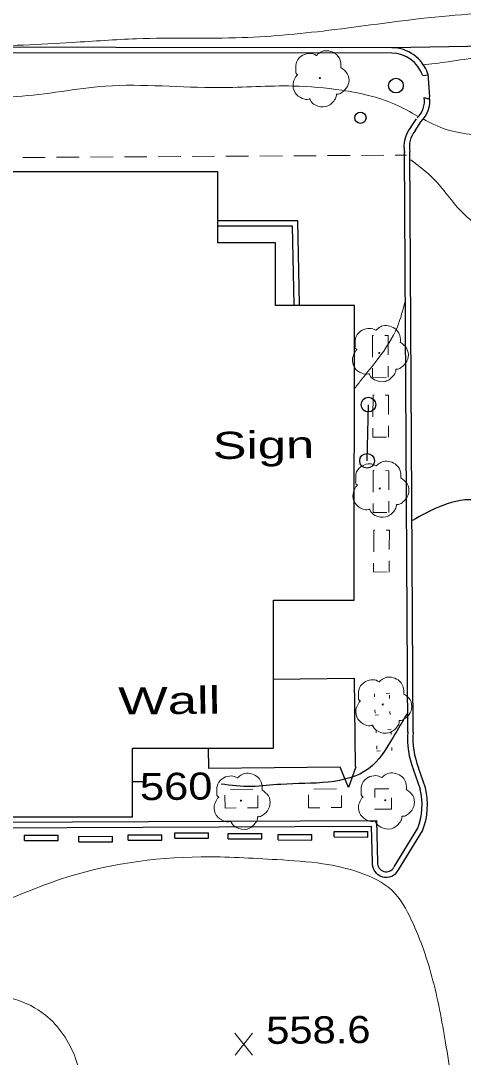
# Model space of a CAD drawing. Extents: x 2361708 to 2370558, y 6977955 to 6991887.
# Drawn here: x 2365302.6 to 2365381, y 6981931.3 to 6982114.9 of the extents above; entities that cross this region are included whole.
import ezdxf
from ezdxf.enums import TextEntityAlignment as Align

# ---------------------------------------------------------------- set-up
doc = ezdxf.new("R2010")
doc.units = 0
doc.header["$LTSCALE"] = 1.9
doc.linetypes.add('DOTTED', pattern=[1.5, 0.3, -1.2])
for name, color, linetype, lineweight in [('11', 7, 'Continuous', 25), ('13', 7, 'Continuous', 13), ('18', 7, 'Continuous', 25), ('2', 7, 'Continuous', 25), ('20', 7, 'Continuous', 25), ('21', 7, 'Continuous', 25), ('23', 7, 'Continuous', 25), ('29', 7, 'Continuous', 13), ('31', 7, 'Continuous', 13), ('35', 7, 'Continuous', 13)]:
    doc.layers.add(name, color=color, linetype=linetype, lineweight=lineweight)

msp = doc.modelspace()

# ---------------------------------------------------------------- linework, layer by layer
at = {"layer": '11'}
msp.add_lwpolyline([(2365245.104, 6981973.887), (2365322.397, 6981973.873), (2365322.401, 6981986.073), (2365347.372, 6981986.061), (2365347.383, 6982012.263), (2365361.684, 6982012.259), (2365361.697, 6982064.481), (2365347.716, 6982064.488), (2365347.721, 6982075.569), (2365337.48, 6982075.572), (2365337.48, 6982088.142), (2365281.227, 6982088.157), (2365281.224, 6982074.836), (2365258.733, 6982074.842), (2365258.715, 6982043.15), (2365245.154, 6982043.161)], close=True, dxfattribs=at)
at = {"layer": '13'}
for p, q in [((2365306.944, 6982090.712), (2365302.944, 6982090.684)), ((2365312.944, 6982090.749), (2365308.944, 6982090.721)), ((2365318.944, 6982090.786), (2365314.944, 6982090.758)), ((2365324.944, 6982090.823), (2365320.944, 6982090.795)), ((2365330.944, 6982090.86), (2365326.944, 6982090.832)), ((2365336.944, 6982090.897), (2365332.944, 6982090.869)), ((2365342.944, 6982090.935), (2365338.944, 6982090.906)), ((2365348.944, 6982090.972), (2365344.944, 6982090.943)), ((2365354.944, 6982091.009), (2365350.944, 6982090.98)), ((2365360.944, 6982091.046), (2365356.944, 6982091.018)), ((2365366.944, 6982091.083), (2365362.944, 6982091.055)), ((2365370.944, 6982091.101), (2365368.944, 6982091.092)), ((2365367.668, 6982051.748), (2365367.679, 6982053.748)), ((2365367.739, 6982041.148), (2365367.75, 6982043.148)), ((2365367.776, 6982027.797), (2365367.787, 6982029.798)), ((2365367.866, 6982017.258), (2365367.877, 6982019.258)), ((2365343.731, 6981978.786), (2365339.732, 6981978.748)), ((2365358.532, 6981978.827), (2365354.532, 6981978.789)), ((2365338.761, 6981977.719), (2365338.783, 6981975.439)), ((2365353.562, 6981977.76), (2365353.583, 6981975.48)), ((2365368.246, 6981975.27), (2365368.247, 6981977.27)), ((2365338.783, 6981975.439), (2365340.783, 6981975.458)), ((2365353.583, 6981975.48), (2365355.583, 6981975.499))]:
    msp.add_line(p, q, dxfattribs=at)
for points in [[(2365365.107, 6982059.173), (2365364.937, 6982059.172), (2365364.924, 6982055.342)], [(2365367.69, 6982055.748), (2365367.698, 6982059.158), (2365367.108, 6982059.163)], [(2365364.913, 6982053.342), (2365364.908, 6982051.761), (2365367.328, 6982051.745)], [(2365365.178, 6982048.574), (2365365.008, 6982048.572), (2365364.994, 6982044.742)], [(2365367.761, 6982045.149), (2365367.768, 6982048.559), (2365367.178, 6982048.563)], [(2365364.984, 6982042.742), (2365364.979, 6982041.162), (2365367.399, 6982041.145)], [(2365365.215, 6982035.224), (2365365.045, 6982035.222), (2365365.032, 6982031.392)], [(2365367.798, 6982031.798), (2365367.805, 6982035.208), (2365367.216, 6982035.213)], [(2365365.021, 6982029.391), (2365365.016, 6982027.811), (2365367.436, 6982027.794)], [(2365365.305, 6982024.684), (2365365.135, 6982024.682), (2365365.122, 6982020.852)], [(2365367.888, 6982021.258), (2365367.896, 6982024.669), (2365367.306, 6982024.673)], [(2365365.111, 6982018.852), (2365365.106, 6982017.272), (2365367.527, 6982017.255)], [(2365367.812, 6981978.825), (2365365.342, 6981978.832), (2365365.337, 6981977.302)], [(2365342.783, 6981975.477), (2365344.623, 6981975.494), (2365344.602, 6981977.655)], [(2365357.583, 6981975.518), (2365359.423, 6981975.536), (2365359.403, 6981977.695)], [(2365365.336, 6981975.302), (2365365.336, 6981975.272), (2365368.246, 6981975.27)]]:
    msp.add_lwpolyline(points, dxfattribs=at)
at = {"layer": '13', "linetype": 'DOTTED'}
for points in [[(2365365.252, 6981995.692), (2365365.377, 6981991.913), (2365368.027, 6981991.998), (2365367.901, 6981995.777)], [(2365365.552, 6981989.315), (2365365.678, 6981985.536), (2365368.328, 6981985.62), (2365368.201, 6981989.4)]]:
    msp.add_lwpolyline(points, close=True, dxfattribs=at)
at = {"layer": '18'}
for points in [[(2365347.336, 6981998.281), (2365361.685, 6981998.448), (2365361.864, 6981982.799)], [(2365359.165, 6981982.693), (2365335.896, 6981982.432), (2365335.851, 6981986.081)], [(2365361.935, 6981982.73), (2365360.659, 6981979.087), (2365359.165, 6981982.693)]]:
    msp.add_lwpolyline(points, dxfattribs=at)
at = {"layer": '2'}
for p, q in [((2365411.128, 6982110.804), (2365368.322, 6982110.137)), ((2365373.8, 6982105.209), (2365374.759, 6982105.308)), ((2365374.707, 6982105.517), (2365375.036, 6982101.42)), ((2365374.087, 6982101.291), (2365375, 6982101)), ((2365371.657, 6982095.958), (2365372.682, 6982097.538)), ((2365372.463, 6982095.435), (2365373.488, 6982097.016)), ((2365371.147, 6981988.888), (2365370.568, 6982091.717)), ((2365372.107, 6981988.897), (2365371.528, 6982091.726)), ((2365373.384, 6981978.728), (2365372.159, 6981982.257)), ((2365374.291, 6981979.047), (2365373.067, 6981982.576)), ((2365329.903, 6981970.124), (2365329.904, 6981971.084)), ((2365329.904, 6981971.084), (2365335.865, 6981971.071)), ((2365335.864, 6981970.111), (2365335.865, 6981971.071)), ((2365339.345, 6981969.994), (2365339.346, 6981970.954)), ((2365339.346, 6981970.954), (2365345.306, 6981970.941)), ((2365345.305, 6981969.981), (2365345.306, 6981970.941)), ((2365348.197, 6981969.798), (2365348.198, 6981970.758)), ((2365348.198, 6981970.758), (2365354.158, 6981970.745)), ((2365354.158, 6981969.785), (2365354.158, 6981970.745)), ((2365358.133, 6981970.323), (2365358.134, 6981971.283)), ((2365358.134, 6981971.283), (2365364.094, 6981971.27)), ((2365364.093, 6981970.31), (2365364.094, 6981971.27)), ((2365368.724, 6981965.023), (2365372.938, 6981971.894)), ((2365369.538, 6981964.521), (2365373.754, 6981971.392)), ((2365303.236, 6981969.7), (2365303.237, 6981970.66)), ((2365303.236, 6981969.7), (2365309.196, 6981969.687)), ((2365303.237, 6981970.66), (2365309.197, 6981970.647)), ((2365309.196, 6981969.687), (2365309.197, 6981970.647)), ((2365312.879, 6981970.442), (2365318.84, 6981970.429)), ((2365312.879, 6981969.482), (2365312.879, 6981970.442)), ((2365312.879, 6981969.482), (2365318.839, 6981969.469)), ((2365318.839, 6981969.469), (2365318.84, 6981970.429)), ((2365321.646, 6981969.746), (2365321.647, 6981970.706)), ((2365321.646, 6981969.746), (2365327.607, 6981969.732)), ((2365321.647, 6981970.706), (2365327.608, 6981970.692)), ((2365327.607, 6981969.732), (2365327.608, 6981970.692)), ((2365329.903, 6981970.124), (2365335.864, 6981970.111)), ((2365339.345, 6981969.994), (2365345.305, 6981969.981)), ((2365348.197, 6981969.798), (2365354.158, 6981969.785)), ((2365358.133, 6981970.323), (2365364.093, 6981970.31))]:
    msp.add_line(p, q, dxfattribs=at)
for points in [[(2365368.322, 6982110.137), (2365270.457, 6982110.215), (2365203.488, 6982109.787)], [(2365368.322, 6982109.177), (2365270.456, 6982109.255), (2365203.497, 6982108.828)], [(2365193.312, 6982099.82), (2365239.211, 6982100.157), (2365239.197, 6982091.107), (2365244.139, 6982090.994), (2365244.395, 6981972.691), (2365365.635, 6981973.215), (2365365.805, 6981965.846)], [(2365193.322, 6982098.86), (2365238.25, 6982099.188), (2365238.236, 6982090.168), (2365243.178, 6982090.055), (2365243.434, 6981971.731), (2365364.695, 6981972.245), (2365364.846, 6981965.827)], [(2365351.975, 6982064.659), (2365351.683, 6982079.467), (2365337.363, 6982079.471)], [(2365351.014, 6982064.64), (2365350.742, 6982078.508), (2365337.612, 6982078.503)]]:
    msp.add_lwpolyline(points, dxfattribs=at)
for centre, radius, start, end in [((2365368.285, 6982103.364), 5.813, 18.53883, 89.6822), ((2365368.285, 6982103.364), 6.773, 18.53883, 89.6822), ((2365369.99, 6982100.718), 4.133, 313.36768, 7.92934), ((2365369.99, 6982100.718), 5.093, 313.36768, 7.92934), ((2365375.813, 6982092.618), 5.337, 139.93792, 191.75552), ((2365375.813, 6982092.618), 4.377, 139.93792, 191.75552), ((2365386.255, 6981987.812), 15.15, 175.61667, 201.65573), ((2365386.255, 6981987.812), 14.19, 175.61667, 201.65573), ((2365362.069, 6981976.058), 11.621, 338.23027, 13.74501), ((2365362.069, 6981976.058), 12.581, 338.23027, 13.74501), ((2365367.332, 6981965.682), 2.491, 176.66337, 332.25563), ((2365367.332, 6981965.682), 1.531, 176.66337, 332.25563), ((2311712.864, 7003141.482), 57778.093, 338.23902, 338.46862)]:
    msp.add_arc(centre, radius, start, end, dxfattribs=at)
at = {"layer": '20'}
msp.add_circle((2365362.76, 6982097.733), 1, dxfattribs=at)
at = {"layer": '21'}
msp.add_line((2365363.959, 6982036.942), (2365364.204, 6982046.895), dxfattribs=at)
for centre in [(2365364.194, 6982046.905), (2365363.949, 6982036.952)]:
    msp.add_circle(centre, 1.3, dxfattribs=at)
at = {"layer": '23'}
msp.add_circle((2365369.066, 6982103.424), 1.3, dxfattribs=at)
at = {"layer": '29'}
for centre in [(2365355.583, 6982104.755), (2365366.107, 6982056.063), (2365366.196, 6982032.053), (2365366.71, 6981993.796), (2365341.611, 6981976.766), (2365367.181, 6981976.829)]:
    msp.add_circle(centre, 0.1, dxfattribs=at)
for points in [[(2365351.617, 6982105.328), (2365351.637, 6982105.338), (2365351.556, 6982105.407), (2365351.32, 6982106.035), (2365351.358, 6982107.315), (2365352.246, 6982108.614), (2365353.552, 6982109.096), (2365354.674, 6982108.907), (2365354.905, 6982108.779), (2365354.974, 6982108.78), (2365355.024, 6982108.82), (2365355.372, 6982109.114), (2365356.237, 6982109.562), (2365357.448, 6982109.493), (2365358.563, 6982108.904), (2365359.298, 6982107.481), (2365359.306, 6982106.62)], [(2365359.295, 6982106.641), (2365360.435, 6982105.581), (2365360.72, 6982103.994), (2365360.013, 6982102.667), (2365359.358, 6982102.121), (2365358.69, 6982101.905), (2365358.54, 6982101.893), (2365358.521, 6982101.783), (2365358.2, 6982100.88), (2365356.661, 6982099.715), (2365354.768, 6982099.997), (2365353.869, 6982100.939), (2365353.798, 6982101.068), (2365353.678, 6982101.047), (2365352.467, 6982101.165), (2365351.198, 6982102.163), (2365350.852, 6982103.8), (2365351.222, 6982104.824), (2365351.548, 6982105.267), (2365351.617, 6982105.317)], [(2365362.141, 6982056.635), (2365362.161, 6982056.646), (2365362.081, 6982056.715), (2365361.844, 6982057.342), (2365361.882, 6982058.623), (2365362.77, 6982059.922), (2365364.075, 6982060.404), (2365365.198, 6982060.215), (2365365.428, 6982060.087), (2365365.498, 6982060.088), (2365365.548, 6982060.128), (2365365.895, 6982060.421), (2365366.761, 6982060.87), (2365367.972, 6982060.801), (2365369.088, 6982060.212), (2365369.821, 6982058.789), (2365369.829, 6982057.928)], [(2365369.819, 6982057.948), (2365370.959, 6982056.889), (2365371.244, 6982055.302), (2365370.537, 6982053.975), (2365369.882, 6982053.429), (2365369.214, 6982053.213), (2365369.065, 6982053.201), (2365369.046, 6982053.091), (2365368.724, 6982052.188), (2365367.185, 6982051.023), (2365365.292, 6982051.305), (2365364.393, 6982052.247), (2365364.322, 6982052.376), (2365364.202, 6982052.355), (2365362.991, 6982052.473), (2365361.721, 6982053.471), (2365361.376, 6982055.108), (2365361.746, 6982056.131), (2365362.072, 6982056.575), (2365362.141, 6982056.626)], [(2365362.23, 6982032.625), (2365362.25, 6982032.635), (2365362.169, 6982032.704), (2365361.933, 6982033.332), (2365361.971, 6982034.613), (2365362.859, 6982035.911), (2365364.164, 6982036.394), (2365365.286, 6982036.204), (2365365.517, 6982036.076), (2365365.587, 6982036.077), (2365365.637, 6982036.117), (2365365.984, 6982036.411), (2365366.85, 6982036.859), (2365368.061, 6982036.791), (2365369.176, 6982036.201), (2365369.91, 6982034.778), (2365369.918, 6982033.918)], [(2365369.908, 6982033.938), (2365371.048, 6982032.879), (2365371.333, 6982031.292), (2365370.626, 6982029.964), (2365369.971, 6982029.418), (2365369.303, 6982029.202), (2365369.153, 6982029.191), (2365369.134, 6982029.081), (2365368.813, 6982028.177), (2365367.274, 6982027.013), (2365365.381, 6982027.295), (2365364.482, 6982028.236), (2365364.41, 6982028.366), (2365364.291, 6982028.344), (2365363.079, 6982028.463), (2365361.81, 6982029.461), (2365361.465, 6982031.098), (2365361.835, 6982032.122), (2365362.16, 6982032.565), (2365362.23, 6982032.615)], [(2365362.744, 6981994.368), (2365362.764, 6981994.378), (2365362.683, 6981994.448), (2365362.447, 6981995.075), (2365362.485, 6981996.356), (2365363.373, 6981997.654), (2365364.678, 6981998.136), (2365365.8, 6981997.947), (2365366.031, 6981997.82), (2365366.101, 6981997.82), (2365366.151, 6981997.861), (2365366.498, 6981998.154), (2365367.364, 6981998.602), (2365368.575, 6981998.533), (2365369.69, 6981997.945), (2365370.424, 6981996.521), (2365370.432, 6981995.661)], [(2365370.422, 6981995.681), (2365371.562, 6981994.622), (2365371.847, 6981993.035), (2365371.14, 6981991.708), (2365370.485, 6981991.162), (2365369.817, 6981990.945), (2365369.667, 6981990.934), (2365369.648, 6981990.824), (2365369.327, 6981989.921), (2365367.788, 6981988.756), (2365365.895, 6981989.038), (2365364.996, 6981989.979), (2365364.925, 6981990.109), (2365364.805, 6981990.088), (2365363.594, 6981990.206), (2365362.324, 6981991.204), (2365361.979, 6981992.841), (2365362.349, 6981993.864), (2365362.675, 6981994.308), (2365362.744, 6981994.358)], [(2365363.216, 6981977.402), (2365363.236, 6981977.412), (2365363.155, 6981977.481), (2365362.919, 6981978.109), (2365362.957, 6981979.389), (2365363.844, 6981980.688), (2365365.15, 6981981.171), (2365366.272, 6981980.981), (2365366.503, 6981980.853), (2365366.573, 6981980.854), (2365366.623, 6981980.894), (2365366.97, 6981981.188), (2365367.836, 6981981.636), (2365369.046, 6981981.568), (2365370.162, 6981980.978), (2365370.895, 6981979.555), (2365370.904, 6981978.695)], [(2365337.645, 6981977.338), (2365337.665, 6981977.348), (2365337.584, 6981977.418), (2365337.348, 6981978.046), (2365337.386, 6981979.326), (2365338.274, 6981980.625), (2365339.579, 6981981.107), (2365340.701, 6981980.918), (2365340.932, 6981980.79), (2365341.002, 6981980.791), (2365341.052, 6981980.831), (2365341.399, 6981981.124), (2365342.265, 6981981.573), (2365343.475, 6981981.504), (2365344.591, 6981980.915), (2365345.325, 6981979.491), (2365345.333, 6981978.631)], [(2365345.323, 6981978.651), (2365346.463, 6981977.592), (2365346.748, 6981976.005), (2365346.041, 6981974.678), (2365345.386, 6981974.132), (2365344.718, 6981973.916), (2365344.568, 6981973.904), (2365344.549, 6981973.794), (2365344.227, 6981972.891), (2365342.689, 6981971.726), (2365340.796, 6981972.008), (2365339.897, 6981972.95), (2365339.826, 6981973.079), (2365339.706, 6981973.058), (2365338.495, 6981973.176), (2365337.225, 6981974.175), (2365336.879, 6981975.811), (2365337.25, 6981976.835), (2365337.576, 6981977.278), (2365337.645, 6981977.328)], [(2365370.893, 6981978.715), (2365372.033, 6981977.656), (2365372.319, 6981976.068), (2365371.611, 6981974.741), (2365370.956, 6981974.195), (2365370.288, 6981973.979), (2365370.138, 6981973.968), (2365370.12, 6981973.857), (2365369.798, 6981972.954), (2365368.259, 6981971.789), (2365366.366, 6981972.072), (2365365.467, 6981973.013), (2365365.396, 6981973.142), (2365365.276, 6981973.121), (2365364.065, 6981973.24), (2365362.796, 6981974.238), (2365362.45, 6981975.874), (2365362.82, 6981976.898), (2365363.146, 6981977.341), (2365363.216, 6981977.392)]]:
    msp.add_spline(points, degree=3, dxfattribs=at)
at = {"layer": '31', "lineweight": 25}
msp.add_line((2365324.338, 6981980.112), (2365322.288, 6981980.113), dxfattribs=at)
at = {"layer": '31'}
for p, q in [((2365343.659, 6981931.693), (2365340.543, 6981935.544)), ((2365340.58, 6981931.664), (2365343.623, 6981935.573))]:
    msp.add_line(p, q, dxfattribs=at)
at = {"layer": '31', "lineweight": 25}
for points in [[(2365410.227, 6981973.309), (2365410.038, 6981978.497), (2365410.159, 6981997.22), (2365405.175, 6982009.123), (2365399.768, 6982019.372), (2365391.472, 6982026.193), (2365382.815, 6982030.051), (2365376.617, 6982028.762), (2365371.97, 6982026.378)], [(2365371.085, 6981992.257), (2365368.565, 6981988.003), (2365364.218, 6981982.412), (2365357.14, 6981980.044), (2365348.694, 6981979.643), (2365343.487, 6981979.254), (2365338.073, 6981979.672)]]:
    msp.add_spline(points, degree=3, dxfattribs=at)
at = {"layer": '35'}
for points in [[(2365109.402, 6981545.775), (2365131.445, 6981549.695), (2365161.361, 6981558.69), (2365183.98, 6981565.236), (2365205.03, 6981568.516), (2365226.001, 6981575.846), (2365237.057, 6981582.612), (2365238.603, 6981584.107), (2365246.477, 6981596.342), (2365250.991, 6981609.596), (2365252.103, 6981624.127), (2365255.069, 6981626.605), (2365256.719, 6981621.351), (2365258.448, 6981613.117), (2365261.221, 6981603.383), (2365265.255, 6981596.641), (2365271.824, 6981589.383), (2365278.776, 6981581.829), (2365281.528, 6981581.695), (2365286.668, 6981587.994), (2365291.277, 6981595.538), (2365295.634, 6981606.37), (2365294.418, 6981619.56), (2365297.594, 6981630.56), (2365302.729, 6981642.64), (2365306.356, 6981653.435), (2365314.989, 6981660.607), (2365319.684, 6981668.452), (2365316.213, 6981678.01), (2365313.166, 6981687.181), (2365319.859, 6981697.416), (2365326.64, 6981699.43), (2365334.746, 6981700.878), (2365340.746, 6981706.185), (2365344.848, 6981713.384), (2365343.021, 6981718.297), (2365336.43, 6981721.484), (2365326.656, 6981722.951), (2365318.433, 6981723.173), (2365315.821, 6981723.418), (2365315.802, 6981726.479), (2365324.911, 6981732.925), (2365332.876, 6981735.501), (2365340.075, 6981734.64), (2365345.289, 6981734.229), (2365351.365, 6981734.717), (2365358.386, 6981733.654), (2365363.512, 6981730.903), (2365369.601, 6981729.971), (2365376.122, 6981731.963), (2365379.61, 6981730.146), (2365382.411, 6981727.882), (2365389.236, 6981725.317), (2365398.373, 6981725.724), (2365405.868, 6981729.456), (2365411.448, 6981735.799), (2365417.037, 6981742.263), (2365423.139, 6981751.501), (2365430.096, 6981763.358), (2365437.549, 6981776.74), (2365442.735, 6981787.749), (2365451.802, 6981805.876), (2365462.536, 6981827.68), (2365472.723, 6981851.068), (2365482.619, 6981872.653), (2365490.274, 6981889.937), (2365499.076, 6981911.882), (2365507.143, 6981931.109), (2365515.756, 6981950.863), (2365524.787, 6981972.82), (2365534.052, 6981995.429), (2365542.203, 6982016.418), (2365552.168, 6982042.193), (2365561.205, 6982063.57), (2365569.506, 6982083.49), (2365577.612, 6982102.849), (2365582.115, 6982114.062), (2365586.885, 6982124.658), (2365593.024, 6982140.547), (2365599.035, 6982155.155), (2365606.868, 6982174.82), (2365616.146, 6982197.14), (2365625.505, 6982219.35), (2365634.428, 6982240.106), (2365646.14, 6982267.319), (2365654.345, 6982287.778), (2365666.243, 6982315.483), (2365672.813, 6982330.146), (2365677.178, 6982340.138), (2365680.28, 6982347.317)], [(2365676.186, 6982348.709), (2365669.524, 6982334.195), (2365660.54, 6982313.568), (2365647.814, 6982282.625), (2365636.978, 6982257.941), (2365624.242, 6982229.118), (2365608.097, 6982192.873), (2365596.749, 6982165.264), (2365587.378, 6982141.123), (2365580.804, 6982124.64), (2365574.754, 6982112.072), (2365565.831, 6982089.246), (2365556.537, 6982067.486), (2365547.388, 6982045.268), (2365538.366, 6982023.351), (2365526.705, 6981994.089), (2365516.823, 6981968.973), (2365506.885, 6981943.507), (2365496.498, 6981920.078), (2365483.67, 6981891.414), (2365473.587, 6981868.507), (2365463.718, 6981846.302), (2365454.424, 6981827.803), (2365449.108, 6981817.892), (2365443.404, 6981807.797), (2365436.869, 6981803.004), (2365431.569, 6981800.864), (2365422.232, 6981800.525), (2365410.028, 6981800.899), (2365403.44, 6981804.846), (2365394.142, 6981809.808), (2365385.386, 6981812.485), (2365377.881, 6981816.163), (2365373.829, 6981821.645), (2365372.596, 6981830.304), (2365373.713, 6981842.185), (2365376.925, 6981856.696), (2365378.206, 6981872.369), (2365380.617, 6981890.113), (2365381.49, 6981905.622), (2365379.952, 6981920.048), (2365377.978, 6981933.11), (2365375.626, 6981944.839), (2365371.844, 6981955.533), (2365368.393, 6981960.83), (2365362.593, 6981964.035), (2365356.108, 6981965.574), (2365347.981, 6981966.306), (2365334.535, 6981966.799), (2365309.632, 6981962.831), (2365298.232, 6981958.532), (2365286.767, 6981951.633), (2365286.326, 6981944.389), (2365287.51, 6981942.909), (2365295.017, 6981942.241), (2365306.95, 6981938.784), (2365312.304, 6981931.095), (2365312.889, 6981918.96), (2365308.949, 6981908.552), (2365306.75, 6981895.771)], [(2365677.892, 6982348.085), (2365672.529, 6982335.833), (2365660.648, 6982307.429), (2365646.837, 6982274.926), (2365635.036, 6982246.682), (2365622.081, 6982216.677), (2365611.669, 6982191.577), (2365599.553, 6982163.83), (2365592.687, 6982146.534), (2365586.249, 6982129.432), (2365581.466, 6982118.156), (2365576.288, 6982105.356), (2365564.068, 6982076.909), (2365552.851, 6982051.33), (2365543.267, 6982027.538), (2365531.634, 6981996.346), (2365522.275, 6981974.126), (2365508.88, 6981943.016), (2365498.407, 6981916.996), (2365486.732, 6981889.043), (2365472.681, 6981858.638), (2365460.458, 6981831.65), (2365451.237, 6981812.771), (2365440.214, 6981790.985), (2365431.973, 6981776.316), (2365426.085, 6981768.75), (2365419.614, 6981764.528), (2365407.216, 6981764.27), (2365393.489, 6981764.93), (2365388.697, 6981766.264), (2365384.846, 6981770.478), (2365379.432, 6981770.846), (2365371.905, 6981769.514), (2365366.159, 6981770.12), (2365363.621, 6981770.856)], [(2365326.783, 6981453.29), (2365329.976, 6981458.16), (2365344.053, 6981475.395), (2365361.918, 6981501.216), (2365372.671, 6981517.71), (2365385.111, 6981538.889), (2365397.296, 6981563.596), (2365407.375, 6981584.723), (2365416.119, 6981604.297), (2365426.44, 6981628.477), (2365436.776, 6981653.056), (2365445.98, 6981674.775), (2365453.326, 6981692.116), (2365458.767, 6981703.518), (2365463.027, 6981714.119), (2365466.907, 6981726.727), (2365470.863, 6981739.705), (2365476.646, 6981754.17), (2365484.6, 6981775.797), (2365493.674, 6981796.465), (2365502.219, 6981819.117), (2365510.893, 6981840.74), (2365521.377, 6981866.692), (2365530.302, 6981887.188), (2365538.13, 6981907.474), (2365547.935, 6981935.368), (2365557, 6981959.015), (2365565.863, 6981980.771), (2365572.485, 6981997.415), (2365579.94, 6982015.846), (2365585.681, 6982031.492), (2365590.885, 6982044.752), (2365597.257, 6982060.423), (2365604.626, 6982078.445), (2365613.142, 6982097.756), (2365620.363, 6982115.526), (2365626.825, 6982131.138), (2365634.8, 6982150.575), (2365643.428, 6982171.918), (2365650.153, 6982189.263), (2365659.494, 6982211.273), (2365667.482, 6982230.38), (2365675.981, 6982251.552), (2365685.231, 6982273.761), (2365693.814, 6982292.324), (2365702.299, 6982311.865), (2365708.915, 6982325.909), (2365713.381, 6982333.712)], [(2365285.582, 6982140.181), (2365299.201, 6982139.3), (2365322.919, 6982138.646), (2365343.29, 6982137.51), (2365363.096, 6982134.948), (2365388.801, 6982133.513), (2365416.137, 6982131.973), (2365429.989, 6982128.704), (2365432.417, 6982125.788), (2365429.949, 6982122.324), (2365414.928, 6982118.201), (2365396.16, 6982116.852), (2365378.469, 6982115.804), (2365358.211, 6982113.341), (2365341.794, 6982111.934), (2365323.115, 6982111.726), (2365311.721, 6982111.058), (2365294.397, 6982110.283)], [(2365373.712, 6982107.128), (2365378.297, 6982107.642), (2365383.999, 6982108.456), (2365391.349, 6982108.496), (2365395.164, 6982107.992), (2365398.66, 6982107.415), (2365402.452, 6982106.162)], [(2365372.988, 6982097.971), (2365368.828, 6982100.131), (2365359.474, 6982102.602), (2365350.826, 6982103.35), (2365337.699, 6982103.065), (2365317.595, 6982103.324), (2365301.851, 6982101.494), (2365285.169, 6982101.625), (2365275.585, 6982100.954), (2365255.913, 6982101.046), (2365245.182, 6982101.124), (2365235.817, 6982100.575), (2365231.091, 6982100.09)], [(2365400.251, 6982099.95), (2365397.61, 6982097.915), (2365385.03, 6982094.665), (2365375.802, 6982096.508), (2365373.843, 6982097.529)], [(2365442.367, 6981953.554), (2365442.927, 6981957.66), (2365442.549, 6981969.046), (2365443, 6981982.571), (2365448.121, 6982001.461), (2365449.436, 6982011.454), (2365449.436, 6982014.584), (2365447.453, 6982027.536), (2365447.883, 6982041.111), (2365450.827, 6982055.46), (2365452.426, 6982068.096), (2365444.71, 6982072.972), (2365437.341, 6982078.072), (2365424.993, 6982079.904), (2365411.889, 6982075.03), (2365400.478, 6982072.991), (2365390.347, 6982075.095), (2365380.619, 6982081.163), (2365375.774, 6982086.876), (2365371.702, 6982090.258)], [(2365370.67, 6982065.187), (2365369.313, 6982060.694), (2365365.916, 6982055.071), (2365362.982, 6982051.373), (2365361.786, 6982049.832)]]:
    msp.add_spline(points, degree=3, dxfattribs=at)

# ---------------------------------------------------------------- texts
at = {"layer": '18', "width": 1.45}
msp.add_text('Wall', height=4.8, rotation=0.545, dxfattribs=at).set_placement((2365319.874, 6981992.01))
at = {"layer": '20', "width": 1.4}
msp.add_text('Sign', height=4.8, rotation=0.545, dxfattribs=at).set_placement((2365336.614, 6982037.272))
at = {"layer": '31', "width": 1.2}
msp.add_text(' 560 ', height=4.8, rotation=0.545, dxfattribs=at).set_placement((2365330.146, 6981976.897), align=Align.CENTER)
at = {"layer": '31', "width": 1.15}
msp.add_text('558.6', height=4.8, rotation=0.545, dxfattribs=at).set_placement((2365346.101, 6981933.657))

doc.saveas('drawing.dxf')
